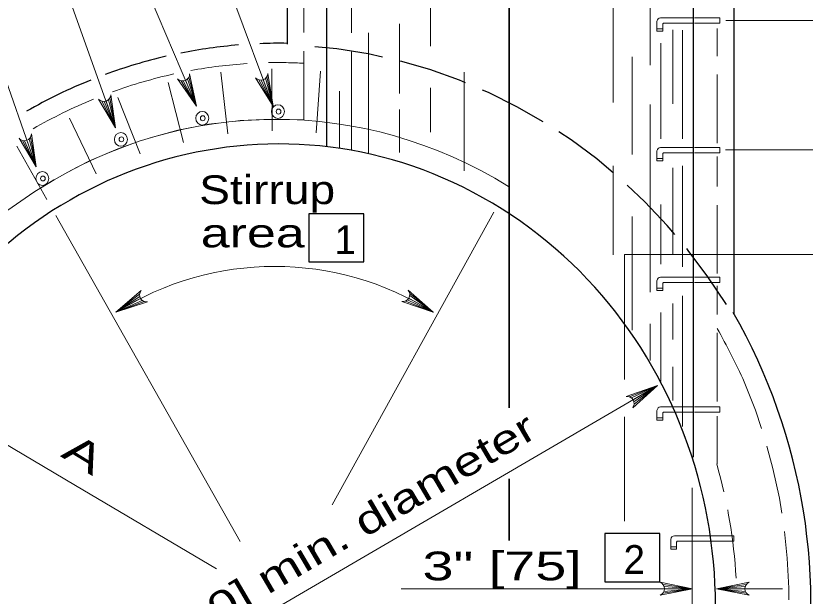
# Model space of a CAD drawing. Extents: x 1170.6 to 1204.6, y 975 to 1019.
# Drawn here: x 1190.902 to 1195.183, y 1002.815 to 1005.964 of the extents above; entities that cross this region are included whole.
import ezdxf
from ezdxf.enums import TextEntityAlignment as Align

# ---------------------------------------------------------------- set-up
doc = ezdxf.new("R2010")
doc.units = 0
doc.header["$LTSCALE"] = 0.062
doc.linetypes.add('LONG_DASHED', pattern=[7.5, 6, -1.5])
doc.linetypes.add('MEDIUM_DASHED', pattern=[4.5, 3, -1.5])
doc.layers.add('1', color=7, linetype='Continuous', lineweight=13)

msp = doc.modelspace()

# ---------------------------------------------------------------- linework, layer by layer
at = {"layer": '1', "lineweight": 25}
for p, q in [((1192.37483, 1005.80992), (1192.37483, 1008.08708)), ((1192.58792, 1005.25275), (1192.58792, 1007.78775)), ((1194.57783, 1003.56833), (1194.57783, 1007.78775)), ((1194.79642, 1007.78775), (1194.79642, 1004.34717))]:
    msp.add_line(p, q, dxfattribs=at)
at = {"layer": '1'}
for p, q in [((1192.72317, 1005.8715), (1192.72317, 1006.8825)), ((1193.15167, 1005.7995), (1193.15167, 1006.4835)), ((1194.34217, 1005.69575), (1194.34217, 1006.16683)), ((1191.01183, 1005.14358), (1190.68867, 1006.06167)), ((1191.44342, 1005.35658), (1191.19133, 1006.06167)), ((1191.88125, 1005.4725), (1191.63117, 1006.06167)), ((1192.29733, 1005.47317), (1192.07917, 1006.06167)), ((1194.14083, 1005.49308), (1194.14083, 1006.02958)), ((1194.57958, 1005.95283), (1194.39908, 1005.95283)), ((1194.57958, 1005.95283), (1194.39908, 1005.95283)), ((1192.98283, 1005.54133), (1192.98283, 1005.91967)), ((1194.37908, 1005.88108), (1194.37908, 1005.93375)), ((1194.37908, 1005.88108), (1194.37908, 1005.93375)), ((1194.41117, 1005.88108), (1194.41117, 1005.91767)), ((1194.41117, 1005.88108), (1194.41117, 1005.91767)), ((1194.57958, 1005.92375), (1194.41733, 1005.92375)), ((1194.57958, 1005.92375), (1194.41733, 1005.92375)), ((1194.75317, 1005.93808), (1198.57708, 1005.93808)), ((1192.814, 1005.2145), (1192.814, 1005.8715)), ((1194.37908, 1005.893), (1194.411, 1005.893)), ((1194.37908, 1005.893), (1194.411, 1005.893)), ((1194.37908, 1005.88108), (1194.411, 1005.88108)), ((1194.37908, 1005.88108), (1194.411, 1005.88108)), ((1194.4655, 1005.486), (1194.4655, 1005.88825)), ((1194.5175, 1005.29675), (1194.5175, 1005.88483)), ((1194.40058, 1005.29675), (1194.40058, 1005.816)), ((1192.72317, 1005.23267), (1192.72317, 1005.76833)), ((1194.24475, 1005.21108), (1194.24475, 1005.74067)), ((1192.01367, 1005.65717), (1192.05175, 1005.32325)), ((1192.29275, 1005.33917), (1192.28958, 1005.67583)), ((1192.555, 1005.66275), (1192.53042, 1005.32933)), ((1193.3335, 1005.12167), (1193.3335, 1005.65817)), ((1191.72875, 1005.60083), (1191.8105, 1005.27575)), ((1191.798, 1005.61125), (1191.88125, 1005.4725)), ((1191.81033, 1005.61058), (1191.88125, 1005.4725)), ((1191.82142, 1005.6135), (1191.88125, 1005.4725)), ((1191.8335, 1005.62175), (1191.88125, 1005.4725)), ((1191.84067, 1005.63142), (1191.88125, 1005.4725)), ((1192.22058, 1005.61558), (1192.29733, 1005.47317)), ((1192.23292, 1005.61442), (1192.29733, 1005.47317)), ((1192.24408, 1005.61675), (1192.29733, 1005.47317)), ((1192.25658, 1005.62442), (1192.29733, 1005.47317)), ((1192.26417, 1005.63375), (1192.29733, 1005.47317)), ((1192.65817, 1005.24342), (1192.65817, 1005.55508)), ((1193.15167, 1005.33175), (1193.15167, 1005.57242)), ((1191.41217, 1005.51758), (1191.44342, 1005.35658)), ((1191.45492, 1005.52042), (1191.5765, 1005.21433)), ((1191.36833, 1005.49992), (1191.44342, 1005.35658)), ((1191.38058, 1005.49858), (1191.44342, 1005.35658)), ((1191.39183, 1005.50083), (1191.44342, 1005.35658)), ((1191.40442, 1005.50833), (1191.44342, 1005.35658)), ((1194.34217, 1004.46458), (1194.34217, 1005.4825)), ((1192.98283, 1005.22142), (1192.98283, 1005.45533)), ((1191.19242, 1005.40767), (1191.3375, 1005.10692)), ((1190.98133, 1005.30475), (1191.01183, 1005.14358)), ((1190.90717, 1005.2555), (1191.07033, 1004.96692)), ((1190.93742, 1005.28733), (1191.01183, 1005.14358)), ((1190.94975, 1005.28592), (1191.01183, 1005.14358)), ((1190.96092, 1005.28808), (1191.01183, 1005.14358)), ((1190.97358, 1005.2955), (1191.01183, 1005.14358)), ((1194.37908, 1005.1775), (1194.37908, 1005.23008)), ((1194.37908, 1005.1775), (1194.37908, 1005.23008)), ((1194.57958, 1005.24925), (1194.39908, 1005.24925)), ((1194.57958, 1005.24925), (1194.39908, 1005.24925)), ((1194.41117, 1005.1775), (1194.41117, 1005.21408)), ((1194.41117, 1005.1775), (1194.41117, 1005.21408)), ((1194.57958, 1005.22017), (1194.41733, 1005.22017)), ((1194.57958, 1005.22017), (1194.41733, 1005.22017)), ((1194.75117, 1005.23642), (1198.57708, 1005.23642)), ((1194.37908, 1005.18942), (1194.411, 1005.18942)), ((1194.37908, 1005.18942), (1194.411, 1005.18942)), ((1194.37908, 1005.1775), (1194.411, 1005.1775)), ((1194.37908, 1005.1775), (1194.411, 1005.1775)), ((1194.14083, 1004.66767), (1194.14083, 1005.14917)), ((1194.4655, 1004.67083), (1194.4655, 1005.13858)), ((1194.5175, 1004.60208), (1194.5175, 1005.14892)), ((1194.40058, 1004.61592), (1194.40058, 1004.93908)), ((1191.11933, 1004.88033), (1192.11925, 1003.11158)), ((1193.49408, 1004.89867), (1192.61792, 1003.30983)), ((1194.24475, 1004.25875), (1194.24475, 1004.874)), ((1194.37908, 1004.47392), (1194.37908, 1004.5265)), ((1194.37908, 1004.47392), (1194.37908, 1004.5265)), ((1194.57958, 1004.54567), (1194.39908, 1004.54567)), ((1194.57958, 1004.54567), (1194.39908, 1004.54567)), ((1194.37908, 1004.48583), (1194.411, 1004.48583)), ((1194.37908, 1004.48583), (1194.411, 1004.48583)), ((1194.41117, 1004.47392), (1194.41117, 1004.51042)), ((1194.41117, 1004.47392), (1194.41117, 1004.51042)), ((1194.57958, 1004.5165), (1194.41733, 1004.5165)), ((1194.57958, 1004.5165), (1194.41733, 1004.5165)), ((1191.57342, 1004.45325), (1191.44467, 1004.35525)), ((1191.57417, 1004.44092), (1191.44467, 1004.35525)), ((1193.03817, 1004.45758), (1193.16633, 1004.35525)), ((1193.03833, 1004.44558), (1193.16633, 1004.35525)), ((1194.37908, 1004.47392), (1194.411, 1004.47392)), ((1194.37908, 1004.47392), (1194.411, 1004.47392)), ((1194.5175, 1003.73608), (1194.5175, 1004.44392)), ((1191.57825, 1004.43017), (1191.44467, 1004.35525)), ((1191.58775, 1004.419), (1191.44467, 1004.35525)), ((1191.59817, 1004.413), (1191.44467, 1004.35525)), ((1193.01625, 1004.41575), (1193.16633, 1004.35525)), ((1193.0265, 1004.42267), (1193.16633, 1004.35525)), ((1193.03358, 1004.43167), (1193.16633, 1004.35525)), ((1194.4655, 1004.20675), (1194.4655, 1004.40258)), ((1194.40058, 1003.98025), (1194.40058, 1004.35442)), ((1194.34217, 1004.09375), (1194.34217, 1004.29258)), ((1194.4655, 1003.87708), (1194.4655, 1004.05883)), ((1194.382, 1003.95808), (1190.26308, 1001.55475)), ((1194.22975, 1003.89708), (1194.382, 1003.95808)), ((1194.24033, 1003.89125), (1194.382, 1003.95808)), ((1194.25008, 1003.88025), (1194.382, 1003.95808)), ((1194.25442, 1003.86967), (1194.382, 1003.95808)), ((1194.25533, 1003.85742), (1194.382, 1003.95808)), ((1194.57958, 1003.84208), (1194.39908, 1003.84208)), ((1194.57958, 1003.84208), (1194.39908, 1003.84208)), ((1194.37908, 1003.77025), (1194.37908, 1003.82292)), ((1194.37908, 1003.77025), (1194.37908, 1003.82292)), ((1194.41117, 1003.77025), (1194.41117, 1003.80683)), ((1194.41117, 1003.77025), (1194.41117, 1003.80683)), ((1194.57958, 1003.81292), (1194.41733, 1003.81292)), ((1194.57958, 1003.81292), (1194.41733, 1003.81292)), ((1194.2025, 1003.22167), (1194.2025, 1003.78875)), ((1194.37908, 1003.78217), (1194.411, 1003.78217)), ((1194.37908, 1003.78217), (1194.411, 1003.78217)), ((1194.37908, 1003.77025), (1194.411, 1003.77025)), ((1194.37908, 1003.77025), (1194.411, 1003.77025)), ((1191.98967, 1002.96333), (1191.22567, 1003.41608)), ((1194.5695, 1002.7625), (1194.5695, 1003.402)), ((1194.45367, 1003.07067), (1194.45367, 1003.12333)), ((1194.45367, 1003.07067), (1194.45367, 1003.12333)), ((1194.66875, 1003.1425), (1194.47367, 1003.1425)), ((1194.61683, 1003.1425), (1194.47367, 1003.1425)), ((1194.67283, 1003.11333), (1194.49183, 1003.11333)), ((1194.62117, 1003.11333), (1194.49183, 1003.11333)), ((1194.45367, 1003.08258), (1194.48558, 1003.08258)), ((1194.45367, 1003.08258), (1194.48558, 1003.08258)), ((1194.45367, 1003.07067), (1194.48558, 1003.07067)), ((1194.45367, 1003.07067), (1194.48558, 1003.07067)), ((1194.48575, 1003.07067), (1194.48575, 1003.10725)), ((1194.48575, 1003.07067), (1194.48575, 1003.10725)), ((1194.4125, 1002.87775), (1194.57275, 1002.85533)), ((1194.41792, 1002.86667), (1194.57275, 1002.85533)), ((1194.86283, 1002.87775), (1194.70258, 1002.85533)), ((1194.85742, 1002.86667), (1194.70258, 1002.85533)), ((1192.99175, 1002.85533), (1194.57275, 1002.85533)), ((1194.41058, 1002.8305), (1194.57275, 1002.85533)), ((1194.41675, 1002.84092), (1194.57275, 1002.85533)), ((1194.41958, 1002.85533), (1194.57275, 1002.85533)), ((1194.70258, 1002.85533), (1195.05975, 1002.85533)), ((1194.85575, 1002.85533), (1194.70258, 1002.85533)), ((1194.85858, 1002.84092), (1194.70258, 1002.85533)), ((1194.86475, 1002.8305), (1194.70258, 1002.85533))]:
    msp.add_line(p, q, dxfattribs=at)
at = {"layer": '1', "linetype": 'LONG_DASHED'}
for p, q in [((1192.46383, 1005.40008), (1192.46383, 1006.10867)), ((1194.70583, 1005.27342), (1194.70583, 1005.895)), ((1194.70583, 1004.56483), (1194.70583, 1005.20083)), ((1194.70583, 1003.87083), (1194.70583, 1004.4995)), ((1194.70583, 1003.5335), (1194.70583, 1003.791))]:
    msp.add_line(p, q, dxfattribs=at)
at = {"layer": '1', "linetype": 'MEDIUM_DASHED'}
for p, q in [((1194.72108, 1005.95283), (1194.58367, 1005.95283)), ((1194.72108, 1005.95283), (1194.58367, 1005.95283)), ((1194.72108, 1005.92383), (1194.72108, 1005.95283)), ((1194.72108, 1005.92383), (1194.72108, 1005.95283)), ((1194.72108, 1005.92375), (1194.58367, 1005.92375)), ((1194.72108, 1005.92375), (1194.58367, 1005.92375)), ((1194.72108, 1005.24925), (1194.58367, 1005.24925)), ((1194.72108, 1005.24925), (1194.58367, 1005.24925)), ((1194.72108, 1005.22017), (1194.58367, 1005.22017)), ((1194.72108, 1005.22017), (1194.58367, 1005.22017)), ((1194.72108, 1005.22025), (1194.72108, 1005.24925)), ((1194.72108, 1005.22025), (1194.72108, 1005.24925)), ((1194.72108, 1004.54567), (1194.58367, 1004.54567)), ((1194.72108, 1004.54567), (1194.58367, 1004.54567)), ((1194.72108, 1004.5165), (1194.72108, 1004.54558)), ((1194.72108, 1004.5165), (1194.72108, 1004.54558)), ((1194.72108, 1004.5165), (1194.58367, 1004.5165)), ((1194.72108, 1004.5165), (1194.58367, 1004.5165)), ((1194.72108, 1003.84208), (1194.58367, 1003.84208)), ((1194.72108, 1003.84208), (1194.58367, 1003.84208)), ((1194.72108, 1003.81292), (1194.72108, 1003.842)), ((1194.72108, 1003.81292), (1194.72108, 1003.842)), ((1194.72108, 1003.81292), (1194.58367, 1003.81292)), ((1194.72108, 1003.81292), (1194.58367, 1003.81292)), ((1194.79567, 1003.1425), (1194.6185, 1003.1425)), ((1194.79567, 1003.11333), (1194.627, 1003.11333)), ((1194.79567, 1003.1425), (1194.67142, 1003.1425)), ((1194.79567, 1003.11333), (1194.67342, 1003.11333)), ((1194.79567, 1003.11333), (1194.79567, 1003.14242)), ((1194.79567, 1003.11333), (1194.79567, 1003.14242))]:
    msp.add_line(p, q, dxfattribs=at)
at = {"layer": '1', "lineweight": 35}
msp.add_line((1193.57775, 1003.45175), (1193.57775, 1003.117), dxfattribs=at)
msp.add_lwpolyline([(1193.57775, 1006.48958), (1193.57775, 1005.58875), (1193.57775, 1003.83592)], dxfattribs=at)
at = {"layer": '1'}
for points in [[(1191.84467, 1005.64925), (1191.88125, 1005.4725), (1191.7795, 1005.62158)], [(1192.269, 1005.65142), (1192.29733, 1005.47317), (1192.20258, 1005.62683)], [(1191.41717, 1005.53517), (1191.44342, 1005.35658), (1191.3505, 1005.51133)], [(1190.98642, 1005.32233), (1191.01183, 1005.14358), (1190.91967, 1005.29883)], [(1194.2025, 1003.9905), (1194.2025, 1004.66792), (1195.30008, 1004.66792), (1195.30008, 1002.65925), (1194.2025, 1002.65925), (1194.2025, 1002.74183)], [(1191.61633, 1004.411), (1191.44467, 1004.35525), (1191.58175, 1004.47275)], [(1193.03058, 1004.47425), (1193.16633, 1004.35525), (1192.99525, 1004.41283)], [(1191.22567, 1003.41608), (1190.316, 1003.95508), (1189.81383, 1004.25258)], [(1194.2115, 1003.89867), (1194.382, 1003.95808), (1194.2475, 1003.83767)], [(1194.39575, 1002.81992), (1194.57275, 1002.85533), (1194.39575, 1002.89075)], [(1194.87958, 1002.81992), (1194.70258, 1002.85533), (1194.87958, 1002.89075)]]:
    msp.add_lwpolyline(points, dxfattribs=at)
at = {"layer": '1', "lineweight": 25}
for points in [[(1192.49133, 1004.88983), (1192.49133, 1004.62825), (1192.79, 1004.62825), (1192.79, 1004.88983)], [(1194.09608, 1003.15417), (1194.09608, 1002.89242), (1194.39467, 1002.89242), (1194.39467, 1003.15417)]]:
    msp.add_lwpolyline(points, close=True, dxfattribs=at)
at = {"layer": '1'}
for centre, start, end in [((1191.80645, 1005.64856), 225.08362, 0.90975), ((1192.23079, 1005.65251), 222.42352, 358.24964), ((1191.37896, 1005.53672), 221.75918, 357.58531), ((1190.94825, 1005.32404), 221.48169, 357.30782), ((1191.61147, 1004.44888), 141.36699, 277.19312), ((1193.0005, 1004.45065), 262.17545, 38.00158), ((1194.21723, 1003.86088), 322.62218, 98.44831), ((1194.38144, 1002.85536), 292.08605, 67.91218), ((1194.89391, 1002.85536), 112.08782, 247.91395)]:
    msp.add_arc(centre, 0.0382, start, end, dxfattribs=at)
for centre, major_axis, start_param, end_param in [((1194.3996, 1005.93098), (0, 0.02191), 0.0230398, 1.4456919), ((1194.3996, 1005.93098), (0, 0.02191), 0.0230398, 1.4456919), ((1194.41694, 1005.91762), (0, 0.00612), 6.2212346, 7.8497314), ((1194.41694, 1005.91762), (0, 0.00612), 6.2212346, 7.8497314), ((1192.31161, 1002.76632), (0, 2.63538), 5.7516932, 6.821497), ((1194.3996, 1005.22739), (0, 0.02191), 0.0230398, 1.4456919), ((1194.3996, 1005.22739), (0, 0.02191), 0.0230398, 1.4456919), ((1194.41694, 1005.21402), (0, 0.00612), 6.2212346, 7.8497314), ((1194.41694, 1005.21402), (0, 0.00612), 6.2212346, 7.8497314), ((1192.30549, 1002.80964), (0, 1.79435), 5.750412, 6.8159586), ((1194.3996, 1004.52379), (0, 0.02191), 0.0230398, 1.4456919), ((1194.3996, 1004.52379), (0, 0.02191), 0.0230398, 1.4456919), ((1194.41694, 1004.51043), (0, 0.00612), 6.2212346, 7.8497314), ((1194.41694, 1004.51043), (0, 0.00612), 6.2212346, 7.8497314), ((1194.3996, 1003.8202), (0, 0.02191), 0.0230398, 1.4456919), ((1194.3996, 1003.8202), (0, 0.02191), 0.0230398, 1.4456919), ((1194.41694, 1003.80683), (0, 0.00612), 6.2212346, 7.8497314), ((1194.41694, 1003.80683), (0, 0.00612), 6.2212346, 7.8497314), ((1194.47417, 1003.1206), (0, 0.02191), 0.0230398, 1.4456919), ((1194.47417, 1003.1206), (0, 0.02191), 0.0230398, 1.4456919), ((1194.49151, 1003.10723), (0, 0.00612), 6.2212346, 7.8497314), ((1194.49151, 1003.10723), (0, 0.00612), 6.2212346, 7.8497314)]:
    msp.add_ellipse(centre, major_axis=major_axis, ratio=0.944544, start_param=start_param, end_param=end_param, dxfattribs=at)
at = {"layer": '1', "lineweight": 25}
for centre, major_axis, start_param, end_param in [((1192.33349, 1002.76462), (0, 3.04986), 6.2688283, 6.3208404), ((1192.33349, 1002.76462), (0, 3.04986), 0.078028, 0.1872275), ((1192.33349, 1002.76462), (0, 3.04986), 0.2157798, 0.3351713), ((1192.32696, 1002.75942), (0, 2.50862), 4.2253836, 7.3170107), ((1192.33349, 1002.76462), (0, 3.04986), 0.3634352, 0.4968155), ((1192.33349, 1002.76462), (0, 3.04986), 0.5380125, 3.4065639), ((1192.33349, 1002.76462), (0, 3.04986), 3.7685949, 5.2606747), ((1192.32696, 1002.75942), (0, 2.50862), 1.0936207, 4.176477)]:
    msp.add_ellipse(centre, major_axis=major_axis, ratio=0.944544, start_param=start_param, end_param=end_param, dxfattribs=at)
at = {"layer": '1', "linetype": 'LONG_DASHED', "lineweight": 25}
msp.add_ellipse((1192.28816, 1002.68139), major_axis=(0, 3.12513), ratio=0.944544, start_param=5.2934334, end_param=6.2217377, dxfattribs=at)
at = {"layer": '1', "linetype": 'LONG_DASHED'}
for centre, major_axis, start_param, end_param in [((1192.32486, 1002.77617), (0, 2.93373), 0.0608974, 0.1715211), ((1192.32486, 1002.77617), (0, 2.93373), 6.2325558, 6.3022473), ((1192.32486, 1002.77617), (0, 2.93373), 0.2055772, 0.3299144), ((1192.32486, 1002.77617), (0, 2.93373), 0.3700269, 0.4998795), ((1192.31467, 1002.75942), (0, 2.64426), 6.2228396, 7.3171666), ((1190.8496, 1001.89051), (0, 4.72435), 5.170059, 5.2396142), ((1192.32486, 1002.77617), (0, 2.93373), 1.1026757, 4.1670365), ((1192.31467, 1002.75942), (0, 2.64426), 1.0870422, 4.1813172), ((1192.32486, 1002.77617), (0, 2.93373), 4.2344755, 5.1344826), ((1192.31467, 1002.75942), (0, 2.64426), 4.7707224, 5.0090392)]:
    msp.add_ellipse(centre, major_axis=major_axis, ratio=0.944544, start_param=start_param, end_param=end_param, dxfattribs=at)
at = {"layer": '1'}
for centre, major_axis in [((1192.32358, 1005.44375), (0, 0.03722)), ((1191.9131, 1005.40777), (0, 0.03722)), ((1192.32665, 1005.44375), (0, 0.01347)), ((1191.91617, 1005.40777), (0, 0.01347)), ((1191.4717, 1005.29333), (0, 0.03722)), ((1191.47477, 1005.29333), (0, 0.01347)), ((1191.0458, 1005.08087), (0, 0.03722)), ((1191.04887, 1005.08087), (0, 0.01347))]:
    msp.add_ellipse(centre, major_axis=major_axis, ratio=0.944544, dxfattribs=at)

# ---------------------------------------------------------------- texts
for s, width, p in [('Stirrup', 1.2, (1192.26512, 1004.942)), ('area  ', 1.35, (1192.26517, 1004.70733)), ('3" [75] ', 1.45, (1193.58154, 1002.901))]:
    msp.add_text(s, height=0.156, dxfattribs=dict(at, width=width)).set_placement(p, align=Align.CENTER)
for s, p in [('1', (1192.63017, 1004.67075)), ('2', (1194.198, 1002.93592))]:
    msp.add_text(s, height=0.156, dxfattribs=at).set_placement(p)
for s, rotation, width, p in [('48" [1200] min. diameter', 30.407, 1.35, (1191.10175, 1002.137)), ('A', 328.565, 1.5, (1191.14025, 1003.57508))]:
    msp.add_text(s, height=0.156, rotation=rotation, dxfattribs=dict(at, width=width)).set_placement(p)

doc.saveas('drawing.dxf')
